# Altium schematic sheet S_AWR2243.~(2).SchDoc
size A3; SheetNumber: 3; SheetTotal: 4; PageSetup: Record=PageOptions¦CenterHorizontal=True¦CenterVertical=True¦PrintScale=1.01¦XCorrection=1.00¦YCorrection=1.00¦PrintKind=1¦BorderSize=5000000¦LeftOffset=0¦BottomOffset=0¦Orientation=2¦PaperLength=1000¦PaperWidth=1000¦Scale=100¦PaperSource=7¦PrintQuality=600¦MediaType=1¦DitherType=10¦PaperKind=A3¦PrintScaleMode=1; SPICEModelCacheFJOGIKSH: <root> / <DocumentId>FJOGIKSH</DocumentId> / </root>
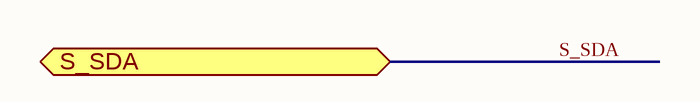
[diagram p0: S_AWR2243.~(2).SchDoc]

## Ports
S_SDA (bidir)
